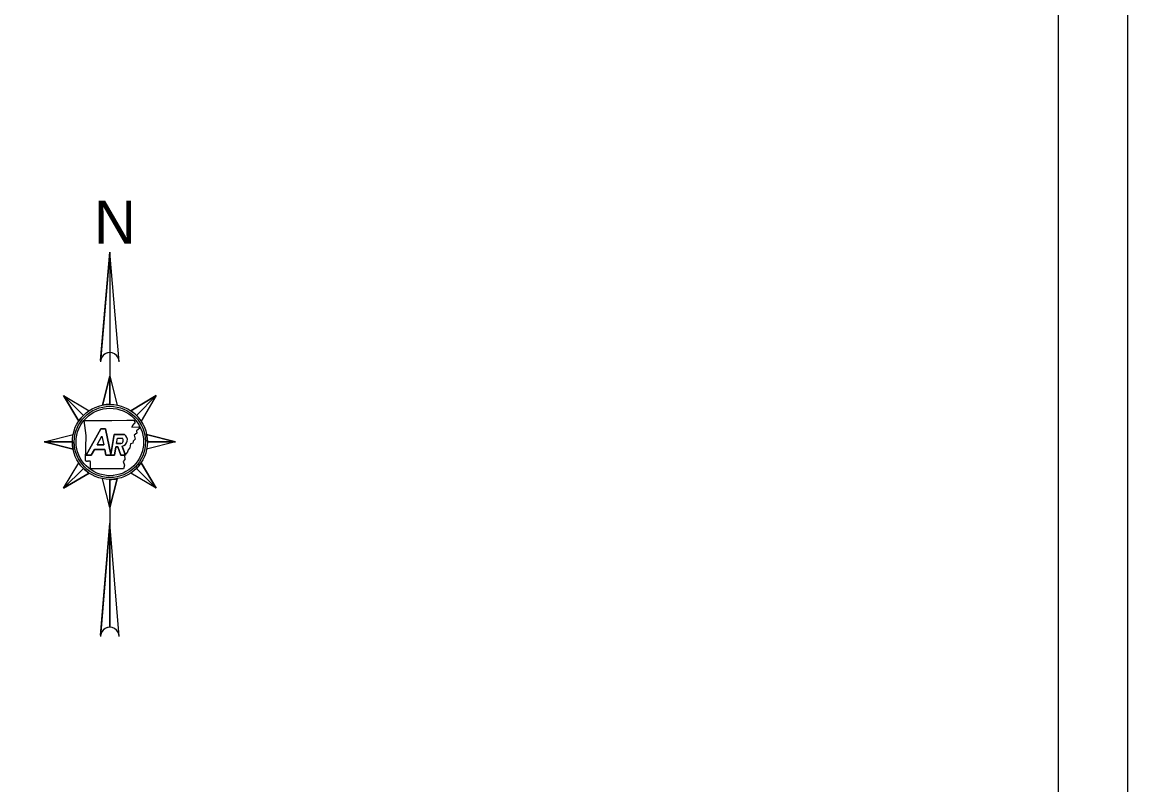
# Model space of a CAD drawing. Extents: x -0.96 to 2.36, y -0.12 to 0.92.
# Drawn here: x 1.0844 to 1.4167, y 0.2292 to 0.4583 of the extents above; entities that cross this region are included whole.
import ezdxf

# ---------------------------------------------------------------- set-up
doc = ezdxf.new("R2010")
doc.units = 0
doc.layers.add('SHET_Border-Lines', color=7, linetype='Continuous')
doc.layers.add('SHET_Border-Text', color=7, linetype='Continuous')

msp = doc.modelspace()

# ---------------------------------------------------------------- linework, layer by layer
at = {"layer": 'SHET_Border-Lines'}
for points in [[(3.6379788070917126e-16, 3.6379788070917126e-16), (1.416663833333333, 3.6379788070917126e-16), (1.416663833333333, 0.9166648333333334), (3.6379788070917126e-16, 0.9166648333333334)], [(0.041666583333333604, 0.02083329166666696), (1.3958305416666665, 0.02083329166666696), (1.3958305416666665, 0.8958315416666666), (0.041666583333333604, 0.8958315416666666)]]:
    msp.add_lwpolyline(points, close=True, dxfattribs=at)
at = {"layer": 'SHET_Border-Text'}
for p, q in [((1.1107546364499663, 0.38918069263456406), (1.1107546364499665, 0.3447032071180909)), ((1.1107546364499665, 0.3519227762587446), (1.1085607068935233, 0.34325730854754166)), ((1.1107546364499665, 0.34347298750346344), (1.1107546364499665, 0.3519227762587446)), ((1.0968131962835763, 0.34614804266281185), (1.102788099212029, 0.34017313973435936)), ((1.102788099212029, 0.34017313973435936), (1.0968131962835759, 0.34614804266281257)), ((1.0968131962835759, 0.34614804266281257), (1.101389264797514, 0.3384692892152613)), ((1.1246960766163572, 0.34614804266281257), (1.1170173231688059, 0.3415719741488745)), ((1.1187211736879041, 0.3401731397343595), (1.1246960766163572, 0.34614804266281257)), ((1.1187211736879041, 0.3401731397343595), (1.1246960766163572, 0.34614804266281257)), ((1.1036392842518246, 0.3282598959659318), (1.1080844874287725, 0.336110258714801)), ((1.1080844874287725, 0.336110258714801), (1.109405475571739, 0.336110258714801)), ((1.1069092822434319, 0.33134124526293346), (1.108363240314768, 0.3339089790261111)), ((1.1120866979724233, 0.334472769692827), (1.115173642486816, 0.334472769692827)), ((1.113048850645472, 0.33336469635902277), (1.1144983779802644, 0.33336469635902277)), ((1.1304708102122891, 0.3322066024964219), (1.121805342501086, 0.33440053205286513)), ((1.091038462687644, 0.3322066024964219), (1.099488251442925, 0.3322066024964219)), ((1.099488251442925, 0.3322066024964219), (1.091038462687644, 0.3322066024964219)), ((1.091038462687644, 0.3322066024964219), (1.0997039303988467, 0.3300126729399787)), ((1.1060972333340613, 0.329907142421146), (1.1051644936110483, 0.3282598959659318)), ((1.1092196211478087, 0.329907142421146), (1.1060972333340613, 0.329907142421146)), ((1.1069092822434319, 0.33134124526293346), (1.1089127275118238, 0.33134124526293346)), ((1.1131292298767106, 0.33075664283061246), (1.1125943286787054, 0.33075664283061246)), ((1.1127566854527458, 0.3316882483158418), (1.1140806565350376, 0.3316882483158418)), ((1.1140516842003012, 0.3282598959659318), (1.1131292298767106, 0.33075664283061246)), ((1.114435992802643, 0.33088983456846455), (1.1154076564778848, 0.3282598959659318)), ((1.122021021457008, 0.3322066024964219), (1.1304708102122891, 0.3322066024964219)), ((1.122021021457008, 0.3322066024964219), (1.1304708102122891, 0.3322066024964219)), ((1.1051644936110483, 0.3282598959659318), (1.1036392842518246, 0.3282598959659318)), ((1.112159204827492, 0.3282598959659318), (1.109572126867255, 0.3282598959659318)), ((1.1154076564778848, 0.3282598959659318), (1.1140516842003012, 0.3282598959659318)), ((1.1246960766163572, 0.3182651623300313), (1.120120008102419, 0.3259439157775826)), ((1.0968131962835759, 0.3182651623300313), (1.1027880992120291, 0.3242400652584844)), ((1.1027880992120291, 0.3242400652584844), (1.0968131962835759, 0.3182651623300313)), ((1.0968131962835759, 0.3182651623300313), (1.1044919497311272, 0.3228412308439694)), ((1.118721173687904, 0.32424006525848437), (1.1246960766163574, 0.3182651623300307)), ((1.118721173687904, 0.32424006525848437), (1.1246960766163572, 0.3182651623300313)), ((1.1107539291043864, 0.3209402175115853), (1.1107546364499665, 0.32094092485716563)), ((1.1107546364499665, 0.3124904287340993), (1.1129485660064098, 0.32115589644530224)), ((1.1107546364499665, 0.3209402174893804), (1.1107546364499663, 0.2848739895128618)), ((1.1107546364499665, 0.3209402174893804), (1.1107546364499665, 0.3124904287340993)), ((1.1107546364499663, 0.3077810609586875), (1.1079762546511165, 0.27416264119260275)), ((1.1107546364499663, 0.2765168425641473), (1.1107546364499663, 0.3077810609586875))]:
    msp.add_line(p, q, dxfattribs=at)
for points in [[(1.1135712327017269, 0.35622651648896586), (1.1107546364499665, 0.38918069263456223), (1.1079380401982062, 0.35622651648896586)], [(1.1079788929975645, 0.35670449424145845), (1.1107546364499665, 0.38918069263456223), (1.1107546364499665, 0.35904311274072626)], [(1.1085607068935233, 0.34325730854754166), (1.1107546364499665, 0.3519227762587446), (1.1129485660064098, 0.34325730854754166)], [(1.1085607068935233, 0.3432573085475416), (1.1107546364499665, 0.3519227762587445), (1.1107546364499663, 0.3434729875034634)], [(1.101389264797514, 0.3384692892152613), (1.0968131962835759, 0.34614804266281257), (1.1044919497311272, 0.3415719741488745)], [(1.101389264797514, 0.3384692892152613), (1.0968131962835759, 0.34614804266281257), (1.102788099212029, 0.34017313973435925)], [(1.1170173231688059, 0.3415719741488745), (1.1246960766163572, 0.34614804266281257), (1.120120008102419, 0.3384692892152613)], [(1.1170173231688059, 0.34157197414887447), (1.1246960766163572, 0.34614804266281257), (1.118721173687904, 0.3401731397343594)], [(1.1030627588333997, 0.3386560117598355), (1.107459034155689, 0.33865329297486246), (1.1113169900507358, 0.33866144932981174), (1.1158682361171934, 0.33873213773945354), (1.117978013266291, 0.33878107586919)], [(1.1033808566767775, 0.32676132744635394), (1.1036255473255, 0.33413739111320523), (1.1030627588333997, 0.3386560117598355), (1.107459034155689, 0.33865329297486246), (1.1113169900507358, 0.33866144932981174), (1.1158682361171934, 0.33873213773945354), (1.117978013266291, 0.33878107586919)], [(1.1033808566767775, 0.32676132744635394), (1.1036255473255, 0.33413739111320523), (1.1030627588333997, 0.3386560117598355)], [(1.115173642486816, 0.334472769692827), (1.1120866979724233, 0.334472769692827), (1.1110405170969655, 0.3284697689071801), (1.109405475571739, 0.336110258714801), (1.1080844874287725, 0.336110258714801), (1.1036392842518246, 0.3282598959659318), (1.1051644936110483, 0.3282598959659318), (1.1060972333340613, 0.329907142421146), (1.1092196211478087, 0.329907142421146), (1.109572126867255, 0.3282598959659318), (1.112159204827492, 0.3282598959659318), (1.1125943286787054, 0.33075664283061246), (1.1131292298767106, 0.33075664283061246), (1.1140516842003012, 0.3282598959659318), (1.1152405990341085, 0.3282598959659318), (1.1151838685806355, 0.32820798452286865), (1.115244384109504, 0.3269192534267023), (1.114702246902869, 0.3263118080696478), (1.1151961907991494, 0.3252059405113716), (1.114854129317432, 0.32410779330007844), (1.1048897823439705, 0.3241241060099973), (1.1048843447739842, 0.32632360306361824)], [(1.109405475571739, 0.336110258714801), (1.1110405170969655, 0.3284697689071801), (1.1120866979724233, 0.334472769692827)], [(1.1173554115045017, 0.33674742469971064), (1.1173255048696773, 0.33665770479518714), (1.1193580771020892, 0.3367621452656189), (1.1197396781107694, 0.336363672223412), (1.1187910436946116, 0.3355841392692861), (1.1188934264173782, 0.3347970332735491), (1.118080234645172, 0.3342606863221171), (1.1183585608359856, 0.33305043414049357), (1.1177314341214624, 0.3324783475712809), (1.1176753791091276, 0.33185618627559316), (1.116912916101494, 0.33158179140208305), (1.1167943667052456, 0.33040855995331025), (1.1162465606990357, 0.32982184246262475), (1.1159817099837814, 0.3289380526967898), (1.1153654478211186, 0.3283741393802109), (1.114435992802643, 0.33088983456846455)], [(1.1193591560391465, 0.33676101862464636), (1.1197396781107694, 0.336363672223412), (1.1187910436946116, 0.3355841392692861), (1.1188934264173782, 0.3347970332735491), (1.118080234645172, 0.3342606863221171), (1.1183585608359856, 0.33305043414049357), (1.1177314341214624, 0.3324783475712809), (1.1176753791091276, 0.33185618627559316), (1.116912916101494, 0.33158179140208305), (1.1167943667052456, 0.33040855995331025), (1.1162465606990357, 0.32982184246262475), (1.1159817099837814, 0.3289380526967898), (1.1151838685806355, 0.32820798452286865), (1.115244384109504, 0.32691925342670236), (1.114702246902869, 0.3263118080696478), (1.1151961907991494, 0.3252059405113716), (1.114854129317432, 0.32410779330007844)], [(1.1173255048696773, 0.33665770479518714), (1.1193890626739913, 0.3367637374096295)], [(1.0997039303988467, 0.3300126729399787), (1.091038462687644, 0.3322066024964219), (1.0997039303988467, 0.33440053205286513)], [(1.108363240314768, 0.3339089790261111), (1.1089127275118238, 0.33134124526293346)], [(1.1127566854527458, 0.3316882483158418), (1.113048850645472, 0.33336469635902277)], [(1.1140806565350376, 0.33168824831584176), (1.1127566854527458, 0.3316882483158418), (1.113048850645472, 0.33336469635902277), (1.1144983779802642, 0.3333646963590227)], [(1.121805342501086, 0.33440053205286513), (1.1304708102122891, 0.3322066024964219), (1.121805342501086, 0.3300126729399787)], [(1.121805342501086, 0.33440053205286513), (1.1304708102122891, 0.3322066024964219), (1.122021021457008, 0.3322066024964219)], [(1.0997039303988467, 0.33001267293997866), (1.091038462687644, 0.3322066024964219), (1.099488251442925, 0.3322066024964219)], [(1.109572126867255, 0.3282598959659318), (1.1092196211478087, 0.329907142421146)], [(1.1125943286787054, 0.33075664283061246), (1.112159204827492, 0.3282598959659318)], [(1.1044919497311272, 0.3228412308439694), (1.0968131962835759, 0.3182651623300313), (1.101389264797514, 0.3259439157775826)], [(1.114854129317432, 0.32410779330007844), (1.1048897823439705, 0.3241241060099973), (1.1048843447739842, 0.32632360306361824)], [(1.120120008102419, 0.3259439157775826), (1.1246960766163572, 0.3182651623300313), (1.117017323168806, 0.3228412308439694)], [(1.120120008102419, 0.3259439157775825), (1.1246960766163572, 0.3182651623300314), (1.118721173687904, 0.3242400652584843)], [(1.104491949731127, 0.3228412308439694), (1.0968131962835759, 0.3182651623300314), (1.1027880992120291, 0.3242400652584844)], [(1.1129485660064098, 0.32115589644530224), (1.1107546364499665, 0.3124904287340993), (1.1085607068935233, 0.32115589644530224)], [(1.1129485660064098, 0.3211558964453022), (1.1107546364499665, 0.3124904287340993), (1.1107546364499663, 0.3209402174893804)], [(1.1135712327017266, 0.27370024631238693), (1.1107546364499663, 0.3077810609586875), (1.107938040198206, 0.27370024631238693)], [(1.1079762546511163, 0.27416264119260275), (1.1107546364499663, 0.3077810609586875), (1.1107546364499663, 0.2765168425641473)]]:
    msp.add_lwpolyline(points, dxfattribs=at)
msp.add_lwpolyline([(1.1089127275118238, 0.33134124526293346), (1.1069092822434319, 0.33134124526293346), (1.108363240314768, 0.3339089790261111)], close=True, dxfattribs=at)
for radius in [0.0112663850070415, 0.010703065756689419, 0.010139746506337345]:
    msp.add_circle((1.1107546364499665, 0.3322066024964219), radius, dxfattribs=at)
for centre, radius, start, end in [((1.1107546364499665, 0.35622651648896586), 0.0028165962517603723, 0, 180.00000000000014), ((1.1107546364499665, 0.35622651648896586), 0.0028165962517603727, 90, 170.22959486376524), ((1.1107546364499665, 0.3322066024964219), 0.011266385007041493, 90.00000000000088, 101.2290882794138), ((1.1107546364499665, 0.33220660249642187), 0.011266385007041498, 90.00000000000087, 101.2290882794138), ((1.1107546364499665, 0.3322066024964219), 0.011266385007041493, 135.00000000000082, 146.22908827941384), ((1.1107546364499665, 0.3322066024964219), 0.0112663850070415, 135.00000000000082, 146.22908827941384), ((1.1107546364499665, 0.3322066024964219), 0.011266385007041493, 45.000000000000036, 56.22908827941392), ((1.1107546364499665, 0.3322066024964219), 0.0112663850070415, 45.000000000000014, 56.2290882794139), ((1.113763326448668, 0.33265758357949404), 0.001019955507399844, 288.12683022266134, 43.89015949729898), ((1.113763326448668, 0.33265758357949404), 0.0010199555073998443, 288.12683022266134, 43.890159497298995), ((1.1140260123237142, 0.33284164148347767), 0.0019944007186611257, 281.8626194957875, 54.87052455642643), ((1.1140260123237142, 0.33284164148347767), 0.0019944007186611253, 281.86261949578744, 54.8705245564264), ((1.1107546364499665, 0.3322066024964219), 0.011266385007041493, 0, 11.229088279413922), ((1.1107546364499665, 0.3322066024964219), 0.011266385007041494, 0, 11.229088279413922), ((1.1107546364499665, 0.3322066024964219), 0.011266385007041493, 180, 191.22908827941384), ((1.1107546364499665, 0.3322066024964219), 0.0112663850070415, 180, 191.22908827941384), ((1.1107546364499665, 0.3322066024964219), 0.011266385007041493, 314.99999999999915, 326.2290882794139), ((1.1107546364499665, 0.3322066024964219), 0.011266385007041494, 314.99999999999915, 326.2290882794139), ((1.1107546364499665, 0.3322066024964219), 0.011266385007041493, 224.99999999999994, 236.2290882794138), ((1.1107546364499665, 0.3322066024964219), 0.0112663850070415, 224.99999999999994, 236.2290882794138), ((1.1107546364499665, 0.3322066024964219), 0.011266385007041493, 269.99999999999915, 281.2290882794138), ((1.1107546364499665, 0.3322066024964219), 0.011266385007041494, 269.9999999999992, 281.2290882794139), ((1.1107546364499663, 0.27370024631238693), 0.0028165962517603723, 0, 180.0000000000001), ((1.1107546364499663, 0.27370024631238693), 0.0028165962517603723, 89.99999999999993, 170.5510966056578), ((1.1107546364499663, 0.27370024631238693), 0.0028165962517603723, 90, 170.5510966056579)]:
    msp.add_arc(centre, radius, start, end, dxfattribs=at)
for points in [[(1.117978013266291, 0.33878107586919), (1.117980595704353, 0.33874102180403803), (1.117985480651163, 0.3387011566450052), (1.1179916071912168, 0.33866144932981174), (1.1179953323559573, 0.33863730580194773), (1.1180214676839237, 0.3386209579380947), (1.1180296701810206, 0.33859891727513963), (1.1180424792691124, 0.33856449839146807), (1.1180151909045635, 0.33851843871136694), (1.118035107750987, 0.3384847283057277), (1.118046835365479, 0.3384648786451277), (1.1180630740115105, 0.33844961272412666), (1.1180813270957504, 0.33843579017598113), (1.1181064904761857, 0.3384167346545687), (1.1181352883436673, 0.33840621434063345), (1.1181601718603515, 0.3383868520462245), (1.118188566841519, 0.3383647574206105), (1.1182127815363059, 0.33834239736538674), (1.118230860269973, 0.33830800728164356), (1.1182468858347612, 0.33827752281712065), (1.1182509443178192, 0.3382460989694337), (1.1182471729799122, 0.33821556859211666), (1.118243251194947, 0.3381838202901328), (1.118227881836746, 0.3381526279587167), (1.118225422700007, 0.3381204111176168), (1.1182227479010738, 0.338085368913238), (1.1182234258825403, 0.33804959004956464), (1.1182199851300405, 0.33801437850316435), (1.1182169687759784, 0.33798351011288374), (1.1182129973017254, 0.33795274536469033), (1.118209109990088, 0.3379219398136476), (1.1182055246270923, 0.3378935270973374), (1.118204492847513, 0.3378650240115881), (1.1181927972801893, 0.33783765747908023), (1.1181799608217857, 0.3378076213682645), (1.1181518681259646, 0.33778989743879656), (1.1181275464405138, 0.3377696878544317), (1.1181070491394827, 0.33775265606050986), (1.1180850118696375, 0.3377381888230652), (1.1180650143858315, 0.33772074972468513), (1.1180446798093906, 0.33770301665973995), (1.1180257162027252, 0.3376839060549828), (1.1180079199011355, 0.33766365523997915), (1.117991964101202, 0.3376454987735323), (1.1179845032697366, 0.3376206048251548), (1.1179671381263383, 0.3376038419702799), (1.1179440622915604, 0.3375815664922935), (1.1179196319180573, 0.337560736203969), (1.1178964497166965, 0.3375385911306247), (1.1178728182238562, 0.33751601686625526), (1.1178491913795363, 0.33749343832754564), (1.117825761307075, 0.3374706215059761), (1.1178060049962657, 0.3374513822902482), (1.1177874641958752, 0.3374310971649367), (1.1177686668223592, 0.33741080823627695), (1.117747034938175, 0.33738745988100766), (1.117728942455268, 0.33736115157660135), (1.1177115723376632, 0.3373346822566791), (1.1176954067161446, 0.3373100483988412), (1.1177038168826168, 0.3372727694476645), (1.1176843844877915, 0.3372503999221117), (1.1176653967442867, 0.33722854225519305), (1.1176411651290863, 0.33721200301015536), (1.1176218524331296, 0.33719058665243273), (1.1176055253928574, 0.3371724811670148), (1.1175892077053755, 0.33715436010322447), (1.1175729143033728, 0.3371362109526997), (1.1175510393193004, 0.3371118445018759), (1.1175292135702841, 0.33708746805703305), (1.1175076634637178, 0.337062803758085), (1.117490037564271, 0.3370426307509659), (1.1174878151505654, 0.33701245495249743), (1.1174750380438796, 0.3369893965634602), (1.117458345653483, 0.3369592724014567), (1.117428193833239, 0.336936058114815), (1.117412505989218, 0.33690511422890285), (1.1174001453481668, 0.33688073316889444), (1.1174094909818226, 0.3368484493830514), (1.1173989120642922, 0.3368235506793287), (1.1173890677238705, 0.3368003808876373), (1.1173700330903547, 0.3367805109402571), (1.1173581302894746, 0.3367582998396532), (1.1173563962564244, 0.33675506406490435), (1.117351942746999, 0.33674975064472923), (1.1173554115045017, 0.33674742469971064)], [(1.1048843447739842, 0.32632360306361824), (1.1048880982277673, 0.32632204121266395), (1.1048938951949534, 0.32631836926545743), (1.1048952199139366, 0.32631816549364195), (1.104902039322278, 0.3263171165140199), (1.1048621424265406, 0.326343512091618), (1.104843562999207, 0.32635350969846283), (1.1048201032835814, 0.3263661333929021), (1.1047989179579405, 0.32638348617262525), (1.1047728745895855, 0.32638885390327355), (1.1047468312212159, 0.3263942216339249), (1.1047201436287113, 0.3263909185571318), (1.1046940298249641, 0.32639429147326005), (1.1046604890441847, 0.3263986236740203), (1.10462697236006, 0.3264035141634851), (1.104593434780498, 0.3264078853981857), (1.1045654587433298, 0.32641153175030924), (1.1045347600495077, 0.32641289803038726), (1.1045091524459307, 0.32641604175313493), (1.1044776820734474, 0.32641990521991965), (1.104451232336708, 0.32648230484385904), (1.1044221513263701, 0.326473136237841), (1.104391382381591, 0.32646343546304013), (1.104360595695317, 0.3264303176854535), (1.1043297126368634, 0.32641332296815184), (1.1042982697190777, 0.3263960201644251), (1.104258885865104, 0.326379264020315), (1.1042263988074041, 0.3263698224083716), (1.104204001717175, 0.3263633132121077), (1.104189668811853, 0.3264182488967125), (1.104166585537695, 0.3264187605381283), (1.1041410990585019, 0.3264193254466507), (1.1041145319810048, 0.32638665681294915), (1.104087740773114, 0.3263861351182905), (1.1040699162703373, 0.3263857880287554), (1.1040510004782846, 0.3264042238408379), (1.104033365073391, 0.3264024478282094), (1.1039975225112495, 0.3263988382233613), (1.1039751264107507, 0.3263394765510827), (1.103938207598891, 0.32633719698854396), (1.1039084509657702, 0.3263353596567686), (1.1038782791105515, 0.3263657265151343), (1.1038484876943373, 0.3263616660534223), (1.1038267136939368, 0.32635869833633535), (1.1038049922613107, 0.3263463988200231), (1.1037832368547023, 0.3263426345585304), (1.1037571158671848, 0.3263381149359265), (1.103727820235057, 0.32633725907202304), (1.1037016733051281, 0.32634535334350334), (1.1036715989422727, 0.326354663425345), (1.1037131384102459, 0.3264260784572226), (1.1036853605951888, 0.32643779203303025), (1.103661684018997, 0.3264477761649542), (1.1036308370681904, 0.3264412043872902), (1.1036065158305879, 0.326451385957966), (1.1035828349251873, 0.3264612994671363), (1.1035523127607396, 0.32646654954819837), (1.1035385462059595, 0.3264894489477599), (1.1035198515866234, 0.32652054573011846), (1.1035069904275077, 0.3265524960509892), (1.103492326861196, 0.32658460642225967), (1.103481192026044, 0.3266089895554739), (1.1034710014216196, 0.32663362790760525), (1.1034597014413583, 0.3266580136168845), (1.1034414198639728, 0.32669746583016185), (1.1034222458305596, 0.32673127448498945), (1.1033808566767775, 0.32676132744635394)]]:
    msp.add_open_spline(points, degree=3, dxfattribs=at)
for points in [[(1.117978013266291, 0.33878107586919), (1.1179916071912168, 0.33866144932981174), (1.1180296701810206, 0.33859891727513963), (1.118035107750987, 0.3384847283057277), (1.1180813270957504, 0.33843579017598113), (1.1181601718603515, 0.3383868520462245), (1.118230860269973, 0.33830800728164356), (1.1182471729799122, 0.33821556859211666), (1.118225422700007, 0.33812041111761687), (1.1182199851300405, 0.33801437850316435), (1.118209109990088, 0.3379219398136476), (1.1181927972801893, 0.33783765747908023), (1.1181275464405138, 0.3377696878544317), (1.1180650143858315, 0.33772074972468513), (1.1180079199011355, 0.33766365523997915), (1.1179671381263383, 0.3376038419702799), (1.1178964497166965, 0.3375385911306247), (1.117825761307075, 0.3374706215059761), (1.1177686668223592, 0.33741080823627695), (1.1177115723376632, 0.3373346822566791), (1.1176843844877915, 0.3372503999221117), (1.1176218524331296, 0.33719058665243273), (1.1175729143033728, 0.3371362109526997), (1.1175076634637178, 0.337062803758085), (1.1174750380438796, 0.3369893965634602), (1.117412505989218, 0.33690511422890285), (1.1173989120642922, 0.3368235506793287), (1.1173581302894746, 0.3367582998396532), (1.1173554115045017, 0.33674742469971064)], [(1.1048843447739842, 0.32632360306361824), (1.1048952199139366, 0.32631816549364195), (1.104843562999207, 0.32635350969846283), (1.1047728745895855, 0.32638885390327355), (1.1046940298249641, 0.32639429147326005), (1.104593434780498, 0.3264078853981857), (1.1045091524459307, 0.32641604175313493), (1.1044221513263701, 0.326473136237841), (1.1043297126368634, 0.32641332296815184), (1.1042263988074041, 0.3263698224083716), (1.104166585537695, 0.3264187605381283), (1.104087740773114, 0.3263861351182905), (1.104033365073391, 0.3264024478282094), (1.103938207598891, 0.32633719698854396), (1.1038484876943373, 0.3263616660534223), (1.1037832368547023, 0.3263426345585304), (1.1037016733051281, 0.32634535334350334), (1.1036853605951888, 0.32643779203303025), (1.1036065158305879, 0.326451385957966), (1.1035385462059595, 0.3264894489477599), (1.103492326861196, 0.32658460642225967), (1.1034597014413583, 0.3266580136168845), (1.1033808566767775, 0.32676132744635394)]]:
    msp.add_spline(points, degree=3, dxfattribs=at)

# ---------------------------------------------------------------- texts
for s, height, p in [('N', 0.012999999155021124, (1.1060046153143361, 0.39173819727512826)), ('DWB 7-27-17', 0.00021906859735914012, (1.1100649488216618, 0.32187915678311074))]:
    msp.add_text(s, height=height, dxfattribs=at).set_placement(p)

doc.saveas('drawing.dxf')
